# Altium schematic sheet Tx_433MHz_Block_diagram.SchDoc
size 594 x 420 mm; APPROVED: Yes; Border_Classification: ?; CmpIndex: 1; ENGINEER: KuRe/SnLe; REVIEWED: Yes; REVISION: 2.0; SymIndex: 1
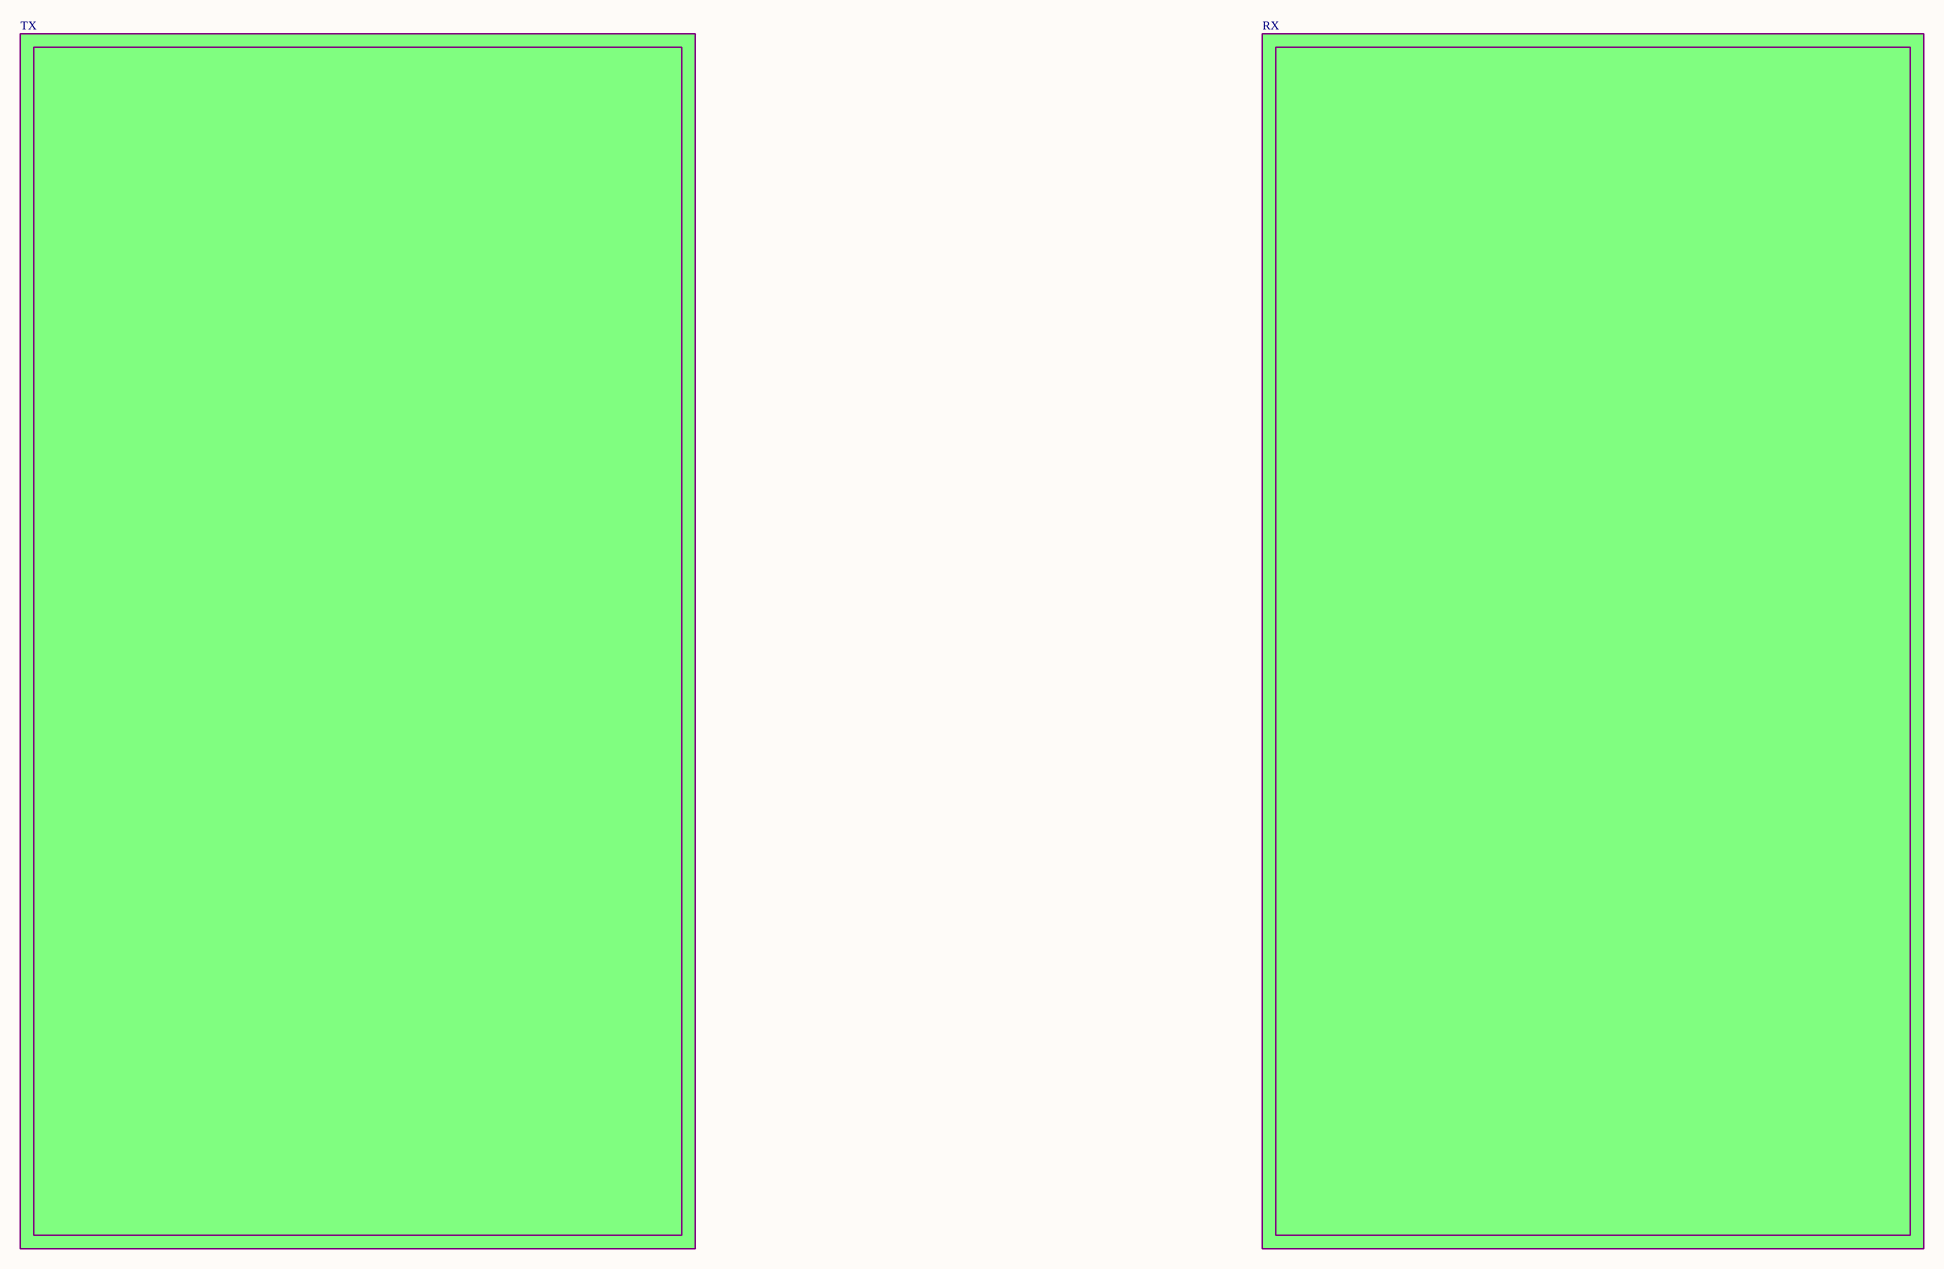
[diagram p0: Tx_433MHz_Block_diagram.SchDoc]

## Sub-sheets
RX = RX.SchDoc: no entries  | CmpIndex: 3; Name: RX; RefDes Renumber: Refresh; RefDes Start: 200; SymIndex: 6
TX = TX.SchDoc: no entries  | CmpIndex: 2; Name: TX; RefDes Renumber: Refresh; RefDes Start: 100; SymIndex: 4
